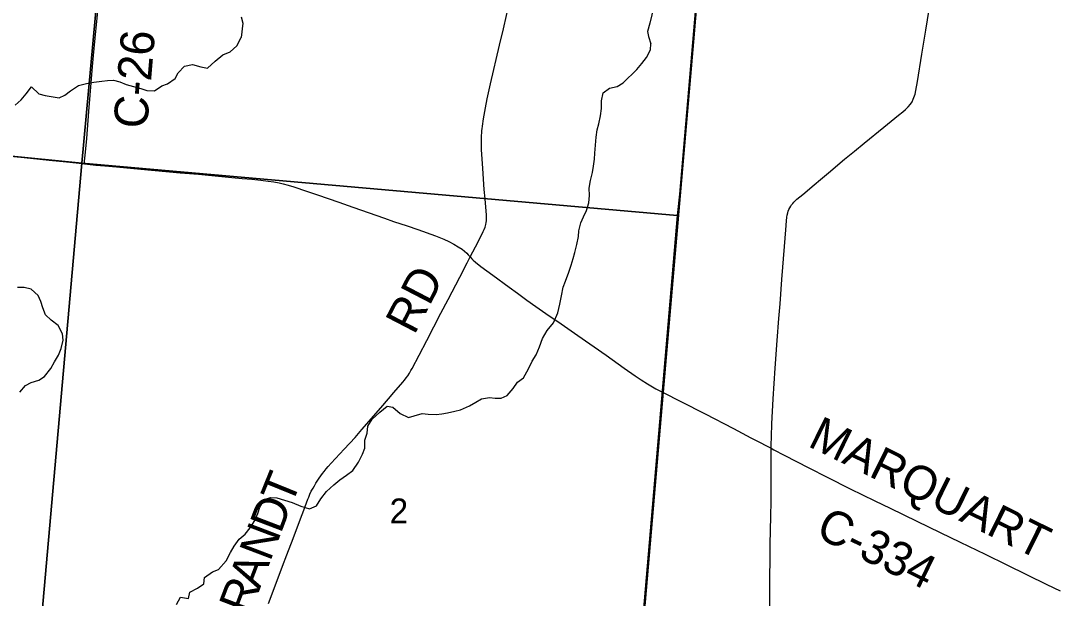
# Model space of a CAD drawing. Extents: x 0 to 1134, y 0 to 440.
# Drawn here: x 834.045 to 835.782, y 367.389 to 368.358 of the extents above; entities that cross this region are included whole.
import ezdxf

# ---------------------------------------------------------------- set-up
doc = ezdxf.new("R2010")
doc.units = 0
for name, color, linetype in [('GM_X_County_Road', 7, 'Continuous'), ('GM_X_County_Road_Text', 7, 'Continuous'), ('GM_X_Minor_River', 7, 'Continuous'), ('GM_X_Section', 7, 'Continuous'), ('GM_X_Section_Text', 7, 'Continuous'), ('GM_X_Unincorporated', 7, 'Continuous'), ('SH_Cut_Line', 7, 'Continuous')]:
    doc.layers.add(name, color=color, linetype=linetype)

msp = doc.modelspace()

# ---------------------------------------------------------------- linework, layer by layer
at = {"layer": 'GM_X_County_Road'}
for points in [[(834.1519, 368.1181), (834.1523, 368.1225), (834.1538, 368.138), (834.156, 368.1605), (834.1595, 368.2058), (834.1656, 368.2818), (834.1671, 368.2999), (834.1699, 368.3292), (834.1731, 368.3626), (834.1766, 368.3997), (834.1797, 368.4343), (834.1884, 368.5309), (834.1956, 368.6113), (834.1981, 368.6407), (834.1995, 368.6574), (834.2039, 368.7065), (834.2063, 368.7313), (834.2079, 368.7498), (834.2106, 368.7789), (834.2145, 368.8216), (834.2165, 368.8414), (834.2193, 368.8714)], [(834.7992, 367.9619), (834.8083, 367.979), (834.8198, 368.0017), (834.8211, 368.0045), (834.8226, 368.008), (834.8242, 368.0121), (834.8247, 368.0142), (834.8253, 368.0164), (834.8259, 368.0196), (834.8265, 368.0226), (834.8267, 368.0258), (834.8266, 368.0289), (834.8264, 368.0321), (834.8241, 368.0594), (834.8227, 368.0754), (834.8202, 368.1101), (834.8184, 368.1424), (834.8181, 368.1496), (834.8182, 368.1616), (834.8184, 368.1669), (834.8185, 368.1693), (834.8186, 368.1714), (834.8189, 368.1739), (834.8192, 368.1769), (834.8197, 368.1813), (834.8215, 368.1935), (834.8247, 368.2119), (834.8278, 368.2271), (834.8334, 368.2525), (834.8484, 368.3173), (834.8548, 368.3445), (834.8652, 368.3893)], [(835.304, 367.641), (835.3041, 367.6459), (835.3047, 367.6609), (835.3054, 367.6821), (835.3072, 367.724), (835.3106, 367.7751), (835.3141, 367.8216), (835.3172, 367.8587), (835.3192, 367.8835), (835.3222, 367.9239), (835.3264, 367.9797), (835.3287, 368.0073), (835.33, 368.0228), (835.3305, 368.0285), (835.3311, 368.0323), (835.3319, 368.0361), (835.3327, 368.0389), (835.3339, 368.0417), (835.3352, 368.0445), (835.3369, 368.0473), (835.3385, 368.0495), (835.3402, 368.0515), (835.3424, 368.054), (835.3473, 368.0587), (835.3574, 368.067), (835.3765, 368.0831), (835.3868, 368.0918), (835.4002, 368.1031), (835.4274, 368.1258), (835.4441, 368.1395), (835.4604, 368.1529), (835.493, 368.18), (835.5176, 368.1997), (835.5248, 368.2056), (835.5296, 368.2096), (835.5342, 368.214), (835.5381, 368.2181), (835.5409, 368.2225), (835.5426, 368.2265), (835.5435, 368.2295), (835.5455, 368.2353), (835.5469, 368.2413), (835.5496, 368.2565), (835.5569, 368.3025), (835.5634, 368.3423), (835.5714, 368.3914)], [(834.0158, 368.1322), (834.051, 368.1286), (834.093, 368.1245), (834.122, 368.1213), (834.143, 368.1191), (834.1519, 368.1181)], [(834.1519, 368.1181), (834.1708, 368.1162), (834.1863, 368.1147), (834.206, 368.1129), (834.2463, 368.1094), (834.3124, 368.1031), (834.3432, 368.1007), (834.3659, 368.0985), (834.4049, 368.0949), (834.4168, 368.0936), (834.4327, 368.0924), (834.4479, 368.0908), (834.46, 368.0892), (834.4696, 368.0879), (834.4784, 368.0864), (834.4856, 368.0846), (834.4939, 368.0825), (834.5034, 368.0796), (834.5246, 368.0724), (834.5427, 368.0661), (834.5786, 368.0538), (834.602, 368.0455), (834.6553, 368.0269), (834.6706, 368.0217), (834.6935, 368.0141), (834.7111, 368.008), (834.741, 367.9972), (834.7548, 367.9916), (834.7633, 367.9877), (834.7717, 367.9834), (834.7792, 367.979), (834.7855, 367.9749), (834.7895, 367.9718), (834.7933, 367.9685), (834.7959, 367.9657), (834.7992, 367.9619)], [(834.4606, 367.3802), (834.4735, 367.4145), (834.4842, 367.443), (834.4915, 367.4622), (834.5019, 367.4895), (834.5147, 367.5225), (834.5201, 367.5371), (834.527, 367.5557), (834.5283, 367.5588), (834.5302, 367.5637), (834.5326, 367.5687), (834.5355, 367.5742), (834.5377, 367.578), (834.5401, 367.5822), (834.5426, 367.5859), (834.5455, 367.5905), (834.5484, 367.5945), (834.5513, 367.5985), (834.5543, 367.6022), (834.5575, 367.6062), (834.5611, 367.6103), (834.5661, 367.616), (834.5879, 367.6392), (834.6063, 367.6592), (834.6176, 367.6725), (834.649, 367.7085), (834.6619, 367.7236), (834.6713, 367.7344), (834.6862, 367.752), (834.6888, 367.7554), (834.6919, 367.7593), (834.6943, 367.7626), (834.6973, 367.767), (834.6998, 367.7714), (834.7017, 367.775), (834.7136, 367.797), (834.7264, 367.8217), (834.7501, 367.8675), (834.7624, 367.8908), (834.782, 367.9282), (834.794, 367.9521), (834.7992, 367.9619)], [(834.7992, 367.9619), (834.8019, 367.9589), (834.8043, 367.9567), (834.8079, 367.9534), (834.8171, 367.9461), (834.837, 367.9313), (834.8647, 367.9112), (834.8783, 367.9014), (834.8944, 367.8897), (834.9094, 367.8788), (834.9261, 367.8669), (834.9518, 367.8495), (834.9798, 367.8299), (835.0272, 367.7969), (835.0576, 367.7754), (835.0758, 367.7624), (835.0861, 367.7555), (835.0967, 367.749), (835.1106, 367.7409), (835.1196, 367.7363), (835.1231, 367.7344)], [(835.1231, 367.7344), (835.1526, 367.7196), (835.1935, 367.6987), (835.2407, 367.6739), (835.2699, 367.6585), (835.2833, 367.6519), (835.2976, 367.6446), (835.304, 367.641)], [(835.3018, 367.3629), (835.3018, 367.3996), (835.3026, 367.4794), (835.3036, 367.5269), (835.3039, 367.5517), (835.3043, 367.5828), (835.3042, 367.6169), (835.304, 367.641)], [(835.304, 367.641), (835.3086, 367.6384), (835.326, 367.6292), (835.3674, 367.6079), (835.3979, 367.5924), (835.4366, 367.5731), (835.4781, 367.5529), (835.5039, 367.5404), (835.5486, 367.5185), (835.5876, 367.4996), (835.6214, 367.4834), (835.6633, 367.463), (835.6996, 367.4451), (835.7666, 367.4124), (835.7891, 367.4018)]]:
    msp.add_lwpolyline(points, dxfattribs=at)
at = {"layer": 'GM_X_Minor_River'}
for points in [[(835.1959, 368.5876), (835.1872, 368.5794), (835.1755, 368.5683), (835.1639, 368.5595), (835.1508, 368.5519), (835.1372, 368.5435), (835.1252, 368.5324), (835.1211, 368.5222), (835.1188, 368.5071), (835.1192, 368.4927), (835.1192, 368.4809), (835.1185, 368.4688), (835.1166, 368.454), (835.1148, 368.4438), (835.1137, 368.4298), (835.1126, 368.4172), (835.1116, 368.4074), (835.1102, 368.3968), (835.1071, 368.3821), (835.1041, 368.3681), (835.1007, 368.3541), (835.0969, 368.3405), (835.0984, 368.3317), (835.1021, 368.3195)], [(834.4147, 368.3647), (834.4175, 368.3544), (834.4147, 368.3302)], [(834.2915, 368.2525), (834.3039, 368.2613), (834.3091, 368.2711), (834.3196, 368.2823), (834.3334, 368.285), (834.347, 368.2809), (834.3587, 368.2787), (834.3715, 368.2906), (834.3843, 368.3013), (834.3966, 368.3063), (834.4079, 368.3163), (834.4147, 368.3302)], [(834.9718, 367.9594), (834.9747, 367.9696), (834.9781, 367.9828), (834.9811, 367.996), (834.9817, 368.0055), (834.9847, 368.0191), (834.9891, 368.0293), (834.9943, 368.0398), (834.998, 368.0527), (834.9994, 368.0648), (834.999, 368.0774), (835.0008, 368.0902), (835.0045, 368.1038), (835.0063, 368.1145), (835.0077, 368.1258), (835.0084, 368.1361), (835.0094, 368.1494), (835.0105, 368.163), (835.012, 368.1751), (835.0152, 368.1853), (835.0178, 368.1986), (835.0193, 368.2111), (835.0192, 368.224), (835.0222, 368.2373), (835.033, 368.2454), (835.046, 368.2481), (835.0557, 368.2544), (835.079, 368.2766), (835.0873, 368.2867), (835.0947, 368.2968), (835.1015, 368.3096), (835.1021, 368.3195)], [(834.0358, 368.2167), (834.0456, 368.2256), (834.0542, 368.2356), (834.0632, 368.2476), (834.0755, 368.2359), (834.086, 368.2326), (834.0993, 368.2304), (834.1095, 368.229), (834.1192, 368.2333), (834.1288, 368.2407), (834.142, 368.2499), (834.1554, 368.253), (834.1676, 368.2554), (834.1809, 368.257), (834.1909, 368.2583), (834.2008, 368.2588), (834.2114, 368.2559), (834.2219, 368.2511), (834.2344, 368.2478), (834.2465, 368.2448), (834.2566, 368.2415), (834.2696, 368.2408), (834.2819, 368.2493), (834.2915, 368.2525)], [(834.3064, 367.3789), (834.3132, 367.391), (834.3265, 367.3887), (834.3286, 367.3997), (834.3417, 367.4063), (834.3525, 367.4132), (834.3532, 367.4239), (834.3667, 367.4338), (834.3771, 367.4374), (834.3896, 367.4519), (834.3971, 367.4662), (834.4031, 367.4767), (834.4118, 367.4886), (834.4215, 367.4968), (834.4301, 367.5072), (834.438, 367.5196), (834.4428, 367.5316), (834.4465, 367.5422), (834.454, 367.555), (834.4644, 367.5581), (834.4746, 367.5579), (834.4875, 367.5538), (834.5003, 367.5501), (834.515, 367.5437), (834.5293, 367.5392), (834.5413, 367.5442), (834.5484, 367.5558), (834.5582, 367.5681), (834.5706, 367.5796), (834.5807, 367.5878), (834.5919, 367.5959), (834.602, 367.6036), (834.6115, 367.6175), (834.6183, 367.631), (834.6223, 367.6412), (834.6222, 367.6545), (834.6263, 367.6662), (834.6277, 367.6779), (834.6349, 367.6899), (834.6473, 367.7014), (834.6601, 367.7114), (834.6696, 367.71), (834.6819, 367.6991), (834.6954, 367.6927), (834.7054, 367.6955), (834.7184, 367.699), (834.7286, 367.6984), (834.7419, 367.6977), (834.7515, 367.6987), (834.761, 367.7003), (834.7733, 367.7031), (834.7828, 367.7052), (834.7978, 367.7121), (834.8086, 367.7183), (834.8183, 367.7241), (834.8316, 367.7261), (834.8411, 367.7251), (834.8514, 367.7249), (834.8614, 367.7296), (834.8715, 367.7412), (834.8786, 367.7516), (834.8887, 367.759), (834.897, 367.774), (834.9034, 367.7872), (834.9098, 367.7977), (834.9154, 367.8113), (834.9203, 367.8252), (834.9282, 367.8383), (834.9388, 367.8514), (834.9464, 367.868), (834.9498, 367.8827), (834.9524, 367.8967), (834.9551, 367.9111), (834.9591, 367.9213), (834.9644, 367.9364), (834.9685, 367.9484), (834.9718, 367.9594)], [(834.0434, 367.7348), (834.0532, 367.746), (834.0628, 367.7511), (834.0754, 367.755), (834.0851, 367.7612), (834.0957, 367.775), (834.102, 367.7859), (834.1084, 367.7972), (834.1128, 367.8081), (834.1162, 367.8225), (834.1149, 367.8331), (834.1077, 367.847), (834.0961, 367.8556), (834.0864, 367.865), (834.0821, 367.8765), (834.079, 367.8872), (834.0746, 367.8972), (834.0623, 367.9081), (834.0506, 367.9107), (834.0396, 367.9109)]]:
    msp.add_lwpolyline(points, dxfattribs=at)
at = {"layer": 'GM_X_Section'}
for points in [[(833.2464, 369.2117), (834.2405, 369.1271), (834.1477, 368.1194), (833.1527, 368.2181)], [(834.2405, 369.1271), (835.233, 369.0338), (835.1501, 368.0674), (835.1466, 368.0316), (834.1477, 368.1194)], [(834.1477, 368.1194), (834.061, 367.1386), (833.0658, 367.2285), (833.1527, 368.2181)], [(834.1477, 368.1194), (835.1466, 368.0316), (835.065, 367.0776), (835.0611, 367.0382), (834.061, 367.1386)]]:
    msp.add_lwpolyline(points, close=True, dxfattribs=at)
at = {"layer": 'GM_X_Unincorporated'}
for points in [[(835.0626, 367.0305), (835.1229, 367.735), (835.1738, 368.323), (835.2208, 368.8787), (835.2574, 369.3181), (832.7638, 369.3181), (832.7638, 366.2539)], [(841.3922, 369.3181), (835.2574, 369.3181), (835.2208, 368.8787), (835.1738, 368.323), (835.1229, 367.735), (835.0626, 367.0305), (835.0377, 366.7503), (835.0373, 366.7416), (834.973, 366.0452), (834.8862, 365.0705), (834.9555, 365.0647), (835.9473, 364.9732), (836.0317, 364.9655), (836.0756, 364.9615), (837.3093, 364.8515), (837.4445, 364.8393), (837.9386, 364.7921), (838.074, 364.7826), (838.4147, 364.746), (839.7495, 364.6071)]]:
    msp.add_lwpolyline(points, dxfattribs=at)
at = {"layer": 'SH_Cut_Line'}
for points in [[(834.8862, 365.0705), (834.973, 366.0452), (835.0373, 366.7416), (835.0377, 366.7503), (835.0626, 367.0305), (835.1229, 367.735), (835.1738, 368.323), (835.2208, 368.8787), (835.2574, 369.3181), (832.7638, 369.3181), (832.7638, 360.1912)], [(846.3638, 369.3181), (835.2574, 369.3181), (835.2208, 368.8787), (835.1738, 368.323), (835.1229, 367.735), (835.0626, 367.0305), (835.0377, 366.7503), (835.0373, 366.7416), (834.973, 366.0452), (834.8862, 365.0705)]]:
    msp.add_lwpolyline(points, dxfattribs=at)

# ---------------------------------------------------------------- texts
at = {"layer": 'GM_X_County_Road_Text'}
for s, height, rotation, p in [('C-26', 0.05682, 85.2129, (834.2569, 368.1759)), ('RD', 0.05682, 62.5595, (834.7053, 367.8296)), ('MARQUART', 0.05682, 333.7529, (835.3637, 367.6453)), ('T', 0.0568, 67.9089, (834.499, 367.5427)), ('D', 0.0568, 69.1579, (834.4813, 367.4963)), ('C-334', 0.05682, 333.9247, (835.3764, 367.4936)), ('N', 0.0568, 69.1798, (834.4635, 367.4495)), ('A', 0.0568, 69.1822, (834.4458, 367.4028)), ('R', 0.0568, 69.1836, (834.4292, 367.3592))]:
    msp.add_text(s, height=height, rotation=rotation, dxfattribs=at).set_placement(p)
at = {"layer": 'GM_X_Section_Text'}
msp.add_text('2', height=0.0419, rotation=0, dxfattribs=at).set_placement((834.6639, 367.5147))

doc.saveas('drawing.dxf')
